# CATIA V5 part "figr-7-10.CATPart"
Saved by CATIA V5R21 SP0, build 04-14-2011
Part number: Part1
Bounding box of the stored display mesh (mm): x -50 to 50, y -62.5 to 62.5, z 0 to 100
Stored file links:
  D:\CATIA V5R21 E-RESOURCES\CATIA-V5R21\catia-v5r21-prt\c07-catia-v5r20-prt\c07-catia-v5r21-figr-7-10.CATPart
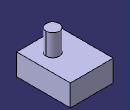
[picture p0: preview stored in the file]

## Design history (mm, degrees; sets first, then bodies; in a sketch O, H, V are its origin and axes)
Body1 (main body)
  Sketch1 on xy-plane, origin (0, 0, 0), H (1, 0, 0), V (0, 1, 0)
    line L1 (-50, 62.5) -> (50, 62.5)
    line L2 (50, 62.5) -> (50, -62.5)
    line L3 (50, -62.5) -> (-50, -62.5)
    line L4 (-50, -62.5) -> (-50, 62.5)
    axis line L5 (50, -62.5) -> (-50, 62.5)
    length L3 = 100
    length L2 = 125
    horizontal: L1 H, L3 H
    vertical: L2 V, L4 V
    midpoint: O L5
  Pad1: profile Sketch1, direction (0, 0, 1), length 50
  Sketch2 on face of Pad1, origin (0, 0, 50), H (1, 0, 0), V (0, 1, 0)
    circle A1 centre (8.7691, -19.7725) radius 15.5717
  Pad2: profile Sketch2, direction (0, 0, 1), length 50
  Sketch3 on face of Pad1, origin (0, 62.5, 112.5), H (1, 0, 0), V (0, 0, -1)
    circle A1 centre (2.1924, 87.7667) radius 15.5717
